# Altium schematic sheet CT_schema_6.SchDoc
size 226 x 144 mm
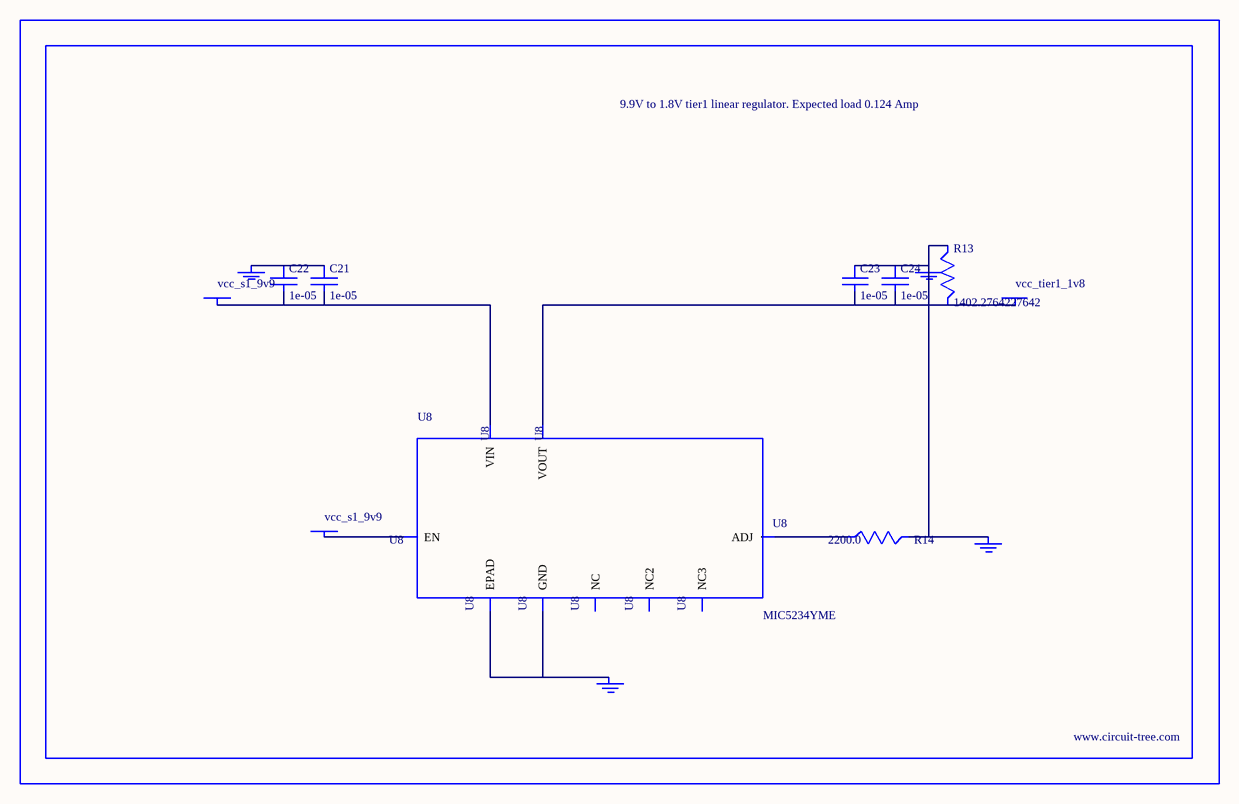
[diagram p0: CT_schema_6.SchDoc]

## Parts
BORDER5  (no value)
C21  1e-05  [C1210]
C22  1e-05  [C1210]
C23  1e-05  [C1210]
C24  1e-05  [C1210]
GND_INSTANCE_5_0  (no value)
GND_INSTANCE_5_1  (no value)
GND_INSTANCE_5_2  (no value)
GND_INSTANCE_5_3  (no value)
POWER_INSTANCE_5_0  vcc_tier1_1v8
POWER_INSTANCE_5_1  vcc_s1_9v9
POWER_INSTANCE_5_2  vcc_s1_9v9
R13  1402.2764227642  [R0603]
R14  2200.0  [R0603]
U8  MIC5234YME  [SOIC-8_EP]

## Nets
NetC21_1: C21.1 C22.1 GND_INSTANCE_5_3.0(GND)
NetC21_2: C21.2 C22.2 POWER_INSTANCE_5_2.0(PWR) U8.8(VIN)
NetC23_1: C23.1 C24.1 GND_INSTANCE_5_0.0(GND) GND_INSTANCE_5_1.0(GND) R13.1 R14.2
NetC23_2: C23.2 C24.2 POWER_INSTANCE_5_0.0(PWR) R13.2 U8.1(VOUT)
NetGND_INSTANCE_5_2_0: GND_INSTANCE_5_2.0(GND) U8.7(GND) U8.EPAD
NetPOWER_INSTANCE_5_1_0: POWER_INSTANCE_5_1.0(PWR) U8.5(EN)
NetR14_1: R14.1 U8.4(ADJ)

Not connected (* = marked no-connect by the designer): U8 2(NC) 3(NC2) 6(NC3)

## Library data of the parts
BORDER5 = BORDER_PAGE5
C21-C24 = C1210C106K5PACTU
GND_INSTANCE_5_0-GND_INSTANCE_5_3 = GND
POWER_INSTANCE_5_0-POWER_INSTANCE_5_2 = PWR
R13 = R13
R14 = RC0603JR-072K2L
